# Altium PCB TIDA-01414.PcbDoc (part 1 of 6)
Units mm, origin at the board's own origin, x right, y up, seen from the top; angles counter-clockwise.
Board outline 400 x 135 mm, 4 copper layers (Top Copper, Copper Layer 2, Copper Layer 3, Bottom Copper), stack 1.567 mm thick; 835 components, 519 nets, 2420 pads, 2045 vias.
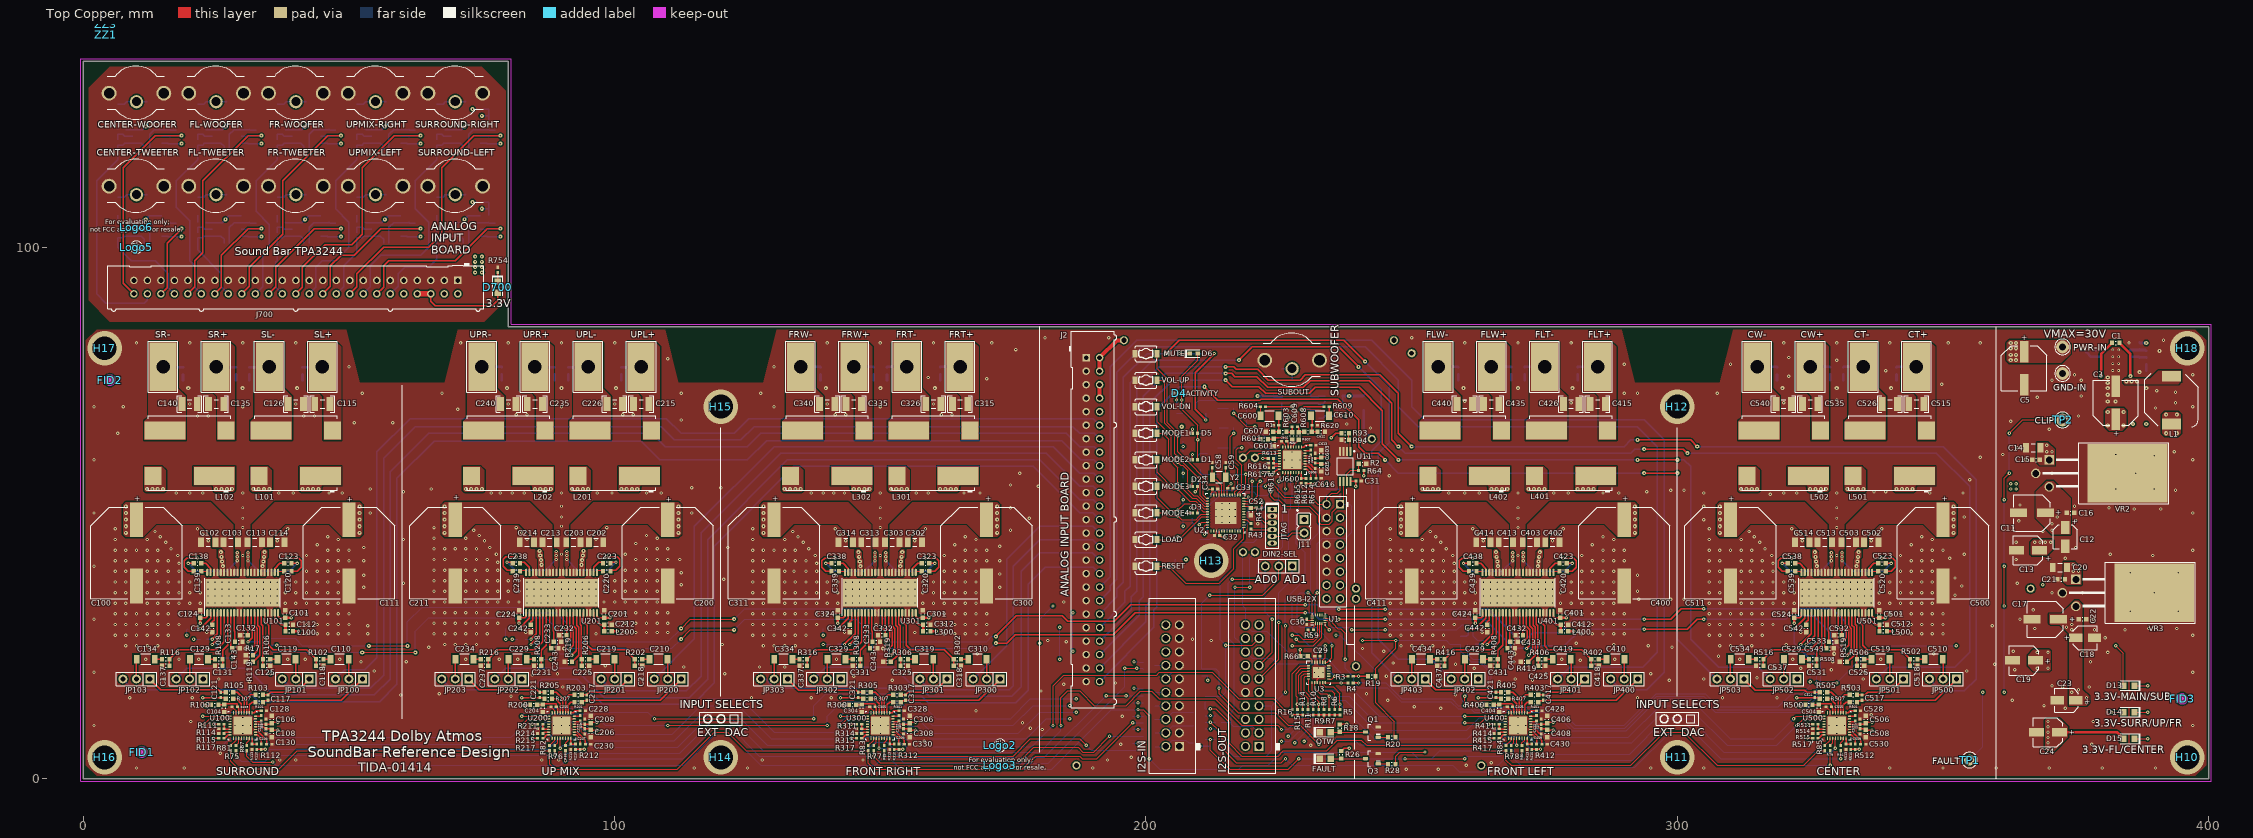
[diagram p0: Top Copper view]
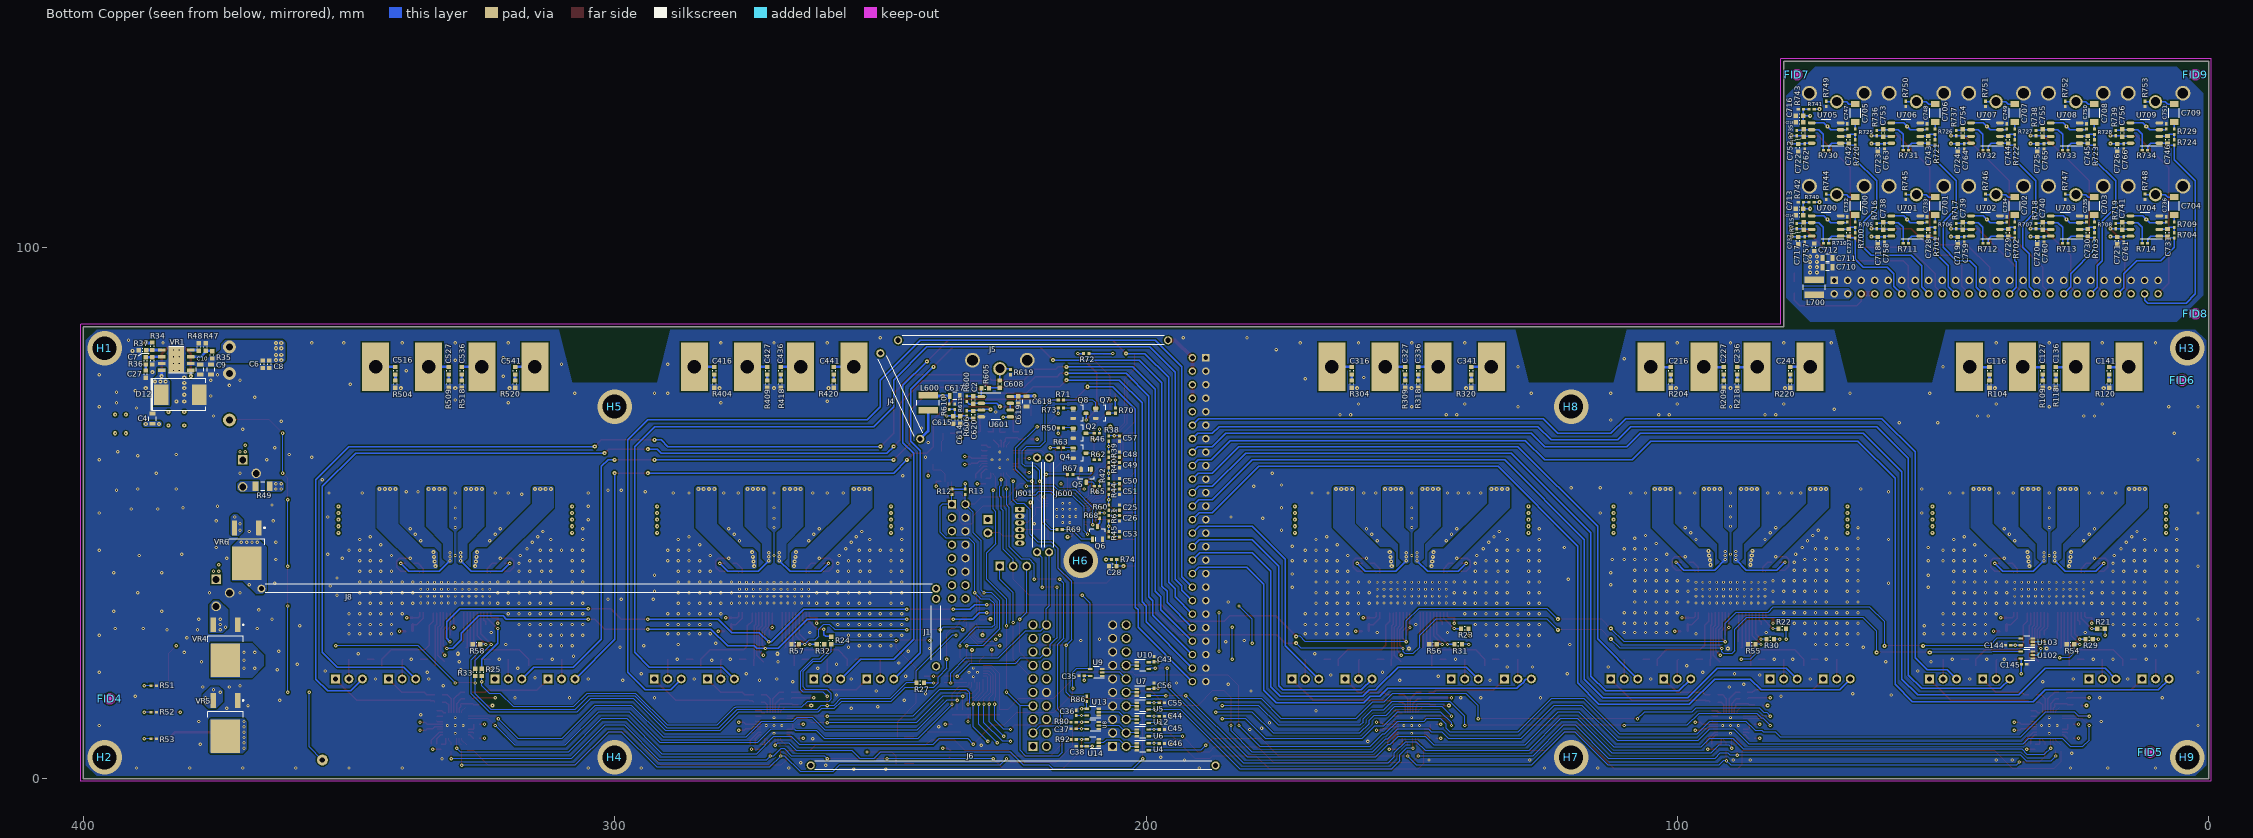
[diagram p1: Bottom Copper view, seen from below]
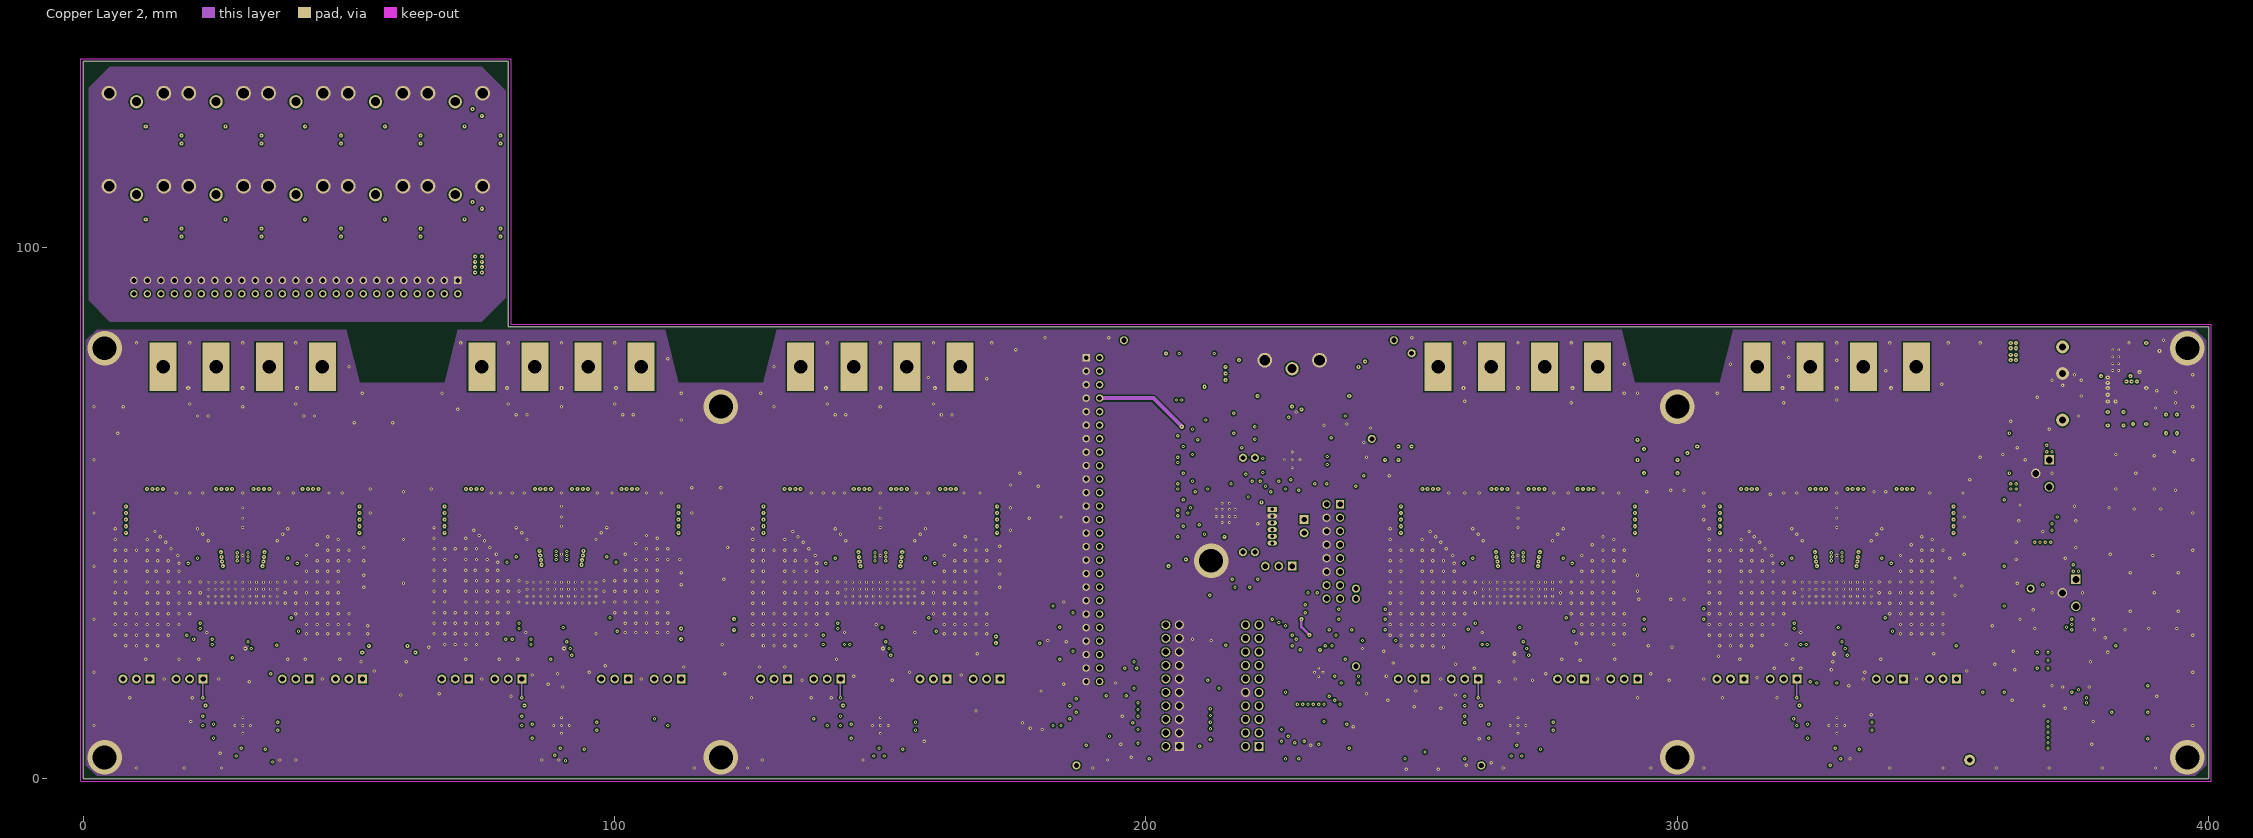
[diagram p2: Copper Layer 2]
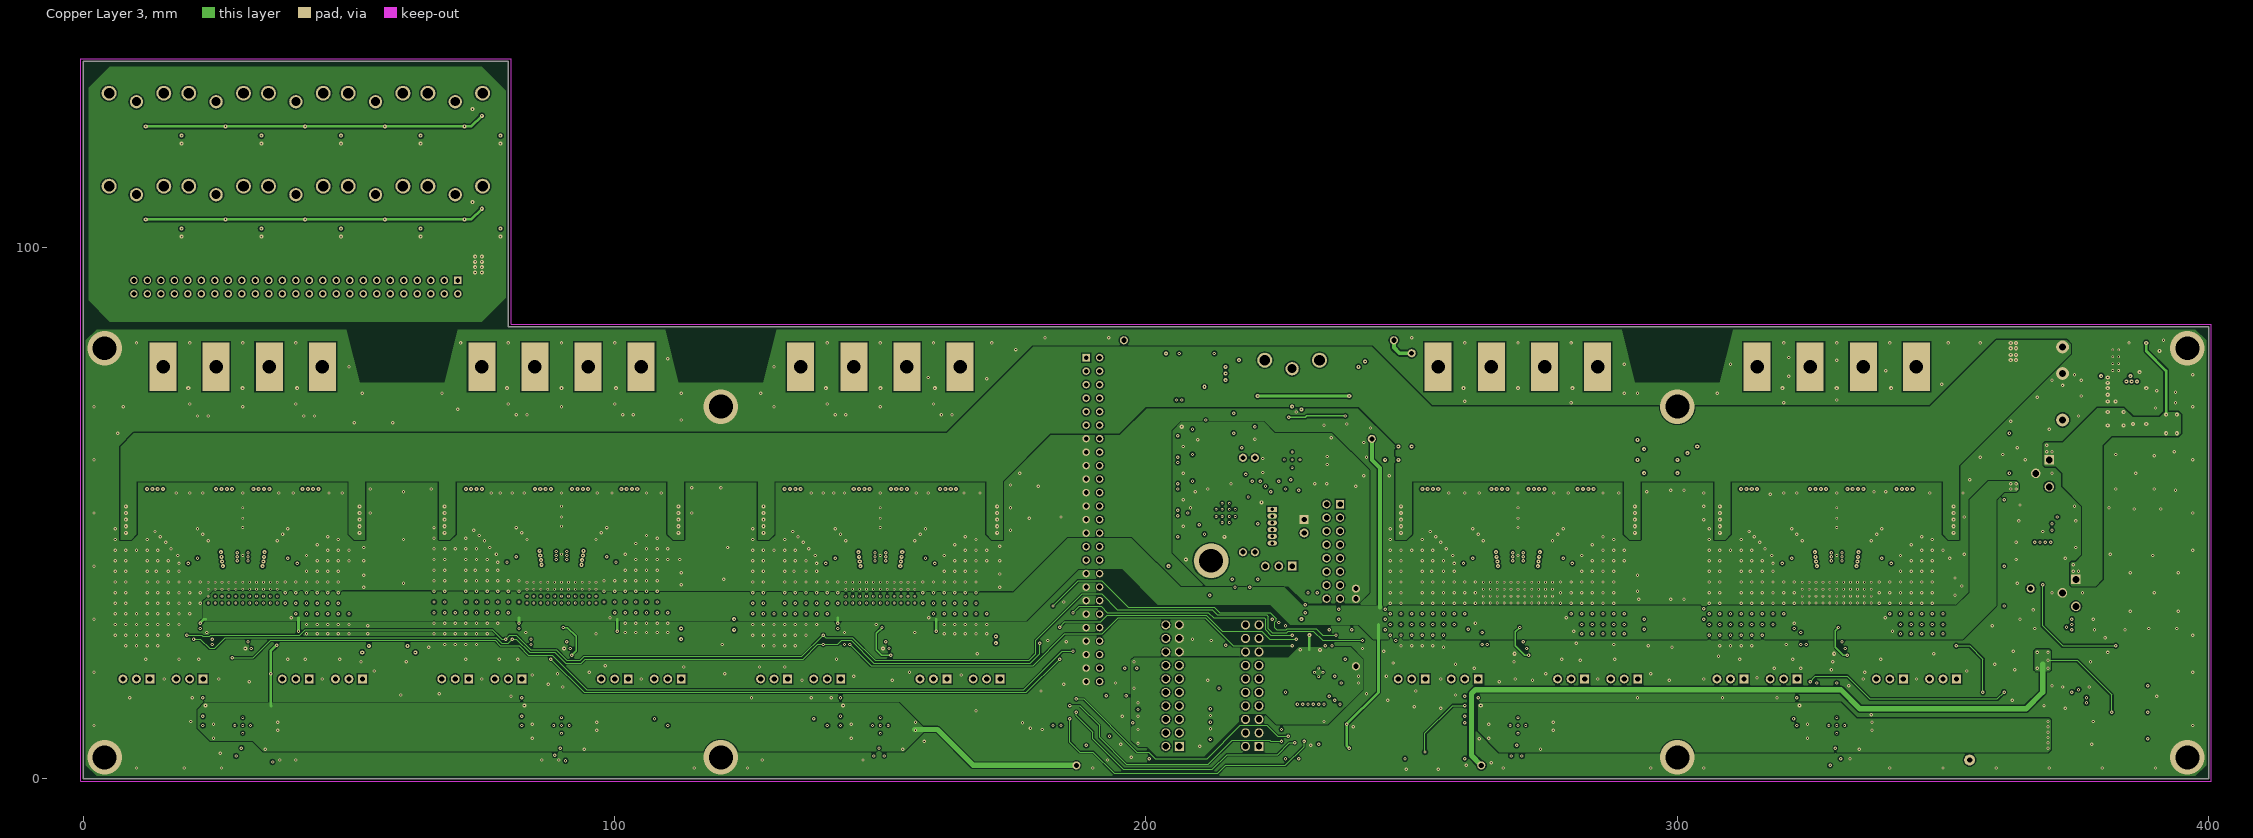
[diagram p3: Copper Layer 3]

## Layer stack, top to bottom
Top SolderMask: solder mask 0.0102, Solder Resist, Dk 3.5
Top Copper: signal copper 0.0696
Dielectric 1: prepreg 0.2032, FR-4, Dk 4.2
Copper Layer 2: signal copper 0.0356
Dielectric 2: core 0.9505, FR-4, Dk 4.2
Copper Layer 3: signal copper 0.0356
Dielectric 3: prepreg 0.2032, FR-4, Dk 4.2
Bottom Copper: signal copper 0.0696
Bottom SolderMask: solder mask 0.0102, Solder Resist, Dk 3.5

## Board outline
0,0 400,0 400,85 80,85 80,135 0,135

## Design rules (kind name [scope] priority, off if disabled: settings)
AcuteAngle [All] p1: minimum=4.50000000000000E+0001 checktracksonly=FALSE
AssemblyTestPointUsage [All] p1: valid=2
BoardOutlineClearance BoardOutlineClearance_MountingHoles [OnCopper and InComponentClass('Mounting Holes')] p1: gap=0.25
BoardOutlineClearance BoardOutlineClearance_Poly [OnCopper and IsPoly] p2: gap=0.25
BoardOutlineClearance [OnCopper and Not InComponentClass('Logo') and not InComponentClass('FiducialMark') and not InRegion(1000,500,4000,800) and not InPoly] p3: gap=0.25
Clearance Clearance_Keepouts [((IsTrack Or IsArc) And Not InPoly) And IsFree and IsKeepOut vs ((IsTrack Or IsArc) And Not InPoly) And IsFree and IsKeepOut] p1: gap=0
Clearance Clearance_Poly [InPolygon] p2: gap=0.25
Clearance [All] p3: gap=0.2
ComponentClearance ComponentClearance_MountingHoles_FiducialMarks [InComponentClass('Mounting Holes') vs InComponentClass('FiducialMark')] p1: gap=0.5 collisioncheckmode=3 verticalgap=0 showdistances=FALSE
ComponentClearance ComponentClearance_Shunt [InComponentClass('Header') vs InComponentClass('Shunt')] p2: gap=0 collisioncheckmode=3 verticalgap=0 showdistances=FALSE
ComponentClearance ComponentClearance_Logo [InComponentClass('Logo')] p3: gap=1 collisioncheckmode=3 verticalgap=0 showdistances=FALSE
ComponentClearance ComponentClearance_ScrewToNut [(HasFootprint('NY PMS 440 0025 PH')) vs (HasFootprint('Keystone_1902C'))] p4: gap=0 collisioncheckmode=3 verticalgap=0 showdistances=FALSE
ComponentClearance ComponentClearance_MountingHoles [InComponentClass('Mounting Holes')] p5: gap=0.5 collisioncheckmode=3 verticalgap=2540 showdistances=FALSE
ComponentClearance ComponentClearance_SmallPassives [HasFootprint('0201*') or HasFootprint('0402*') or HasFootprint('0508') or HasFootprint('0603*') or HasFootprint('0612') or HasFootprint('0805*') or HasFootprint('0815*') or HasFootprint('0830*') or HasFootprint('1206*') or HasFootprint('1210*') or HasFootprint('1808*') or HasFootprint('1812*') or HasFootprint('1825*') or HasFootprint('2010*') or HasFootprint('2220*') or HasFootprint('2225*') or HasFootprint('2512*') or HasFootprint('2728*') or HasFootprint('3518*') or HasFootprint('D0*') or  HasFootprint('DCK*') or HasFootprint('DDW*') or  HasFootprint('NRS*') or HasFootprint('RGE*') or HasFootprint('RGZ*') or HasFootprint('RHB*') or HasFootprint('RSV*') or HasFootprint('SOT*') or HasFootprint('TSSOP*') vs HasFootprint('0201*') or HasFootprint('0402*') or HasFootprint('0508') or HasFootprint('0603*') or HasFootprint('0612') or HasFootprint('0805*') or HasFootprint('0815*') or HasFootprint('0830*') or HasFootprint('1206*') or HasFootprint('1210*') or HasFootprint('1808*') or HasFootprint('1812*') or HasFootprint('1825*') or HasFootprint('2010*') or HasFootprint('2220*') or HasFootprint('2225*') or HasFootprint('2512*') or HasFootprint('2728*') or HasFootprint('3518*') or HasFootprint('D0*') or  HasFootprint('DCK*') or HasFootprint('DDW*') or  HasFootprint('NRS*') or HasFootprint('RGE*') or HasFootprint('RGZ*') or HasFootprint('RHB*') or HasFootprint('RSV*') or HasFootprint('SOT*') or HasFootprint('TSSOP*')] p6: gap=0.25 collisioncheckmode=3 verticalgap=0 showdistances=FALSE
ComponentClearance ComponentClearance_THtoSMT [IsThruComponent vs IsSMTComponent] p7: gap=0.25 collisioncheckmode=3 verticalgap=0 showdistances=FALSE
ComponentClearance ComponentClearance_THtoTH [IsThruComponent vs IsThruComponent] p8: gap=0.25 collisioncheckmode=3 verticalgap=0 showdistances=FALSE
DiffPairsRouting [All] p1: maxlimit=2.54 minlimit=0.254 mostfreqgap=0.254 toplayer_minwidth=0.381 toplayer_maxwidth=0.381 toplayer_prefwidth=0.381 midlayer1_minwidth=0.381 midlayer1_maxwidth=0.381 midlayer1_prefwidth=0.381 midlayer2_minwidth=0.381 midlayer2_maxwidth=0.381 midlayer2_prefwidth=0.381 bottomlayer_minwidth=0.381 bottomlayer_maxwidth=0.381 bottomlayer_prefwidth=0.381 maxuncoupledlength=25.4
FabricationTestPointUsage TestPointUsage [All] p1: valid=2 allowmultiple=FALSE
FabricationTestpoint Testpoint [All] p1: side=3 testpointundercomponent=TRUE minsize=1.016 maxsize=2.54 preferedsize=1.524 minholesize=0 maxholesize=1.016 preferedholesize=0.813 testpointgrid=0.025 allowsidetop=TRUE allowsidebottom=TRUE usegrid=TRUE gridtolerance=0
FanoutControl Fanout_LCC [IsLCC] p1: bgadir=Out bgaviamode=Centered fanoutstyle=Auto fanoutdirection=Alternating viagrid=0.025 // Fanout_LCC (Default Rule)
FanoutControl Fanout_BGA [IsBGA] p2: bgadir=Out bgaviamode=Centered fanoutstyle=Auto fanoutdirection=Alternating viagrid=0.025 // Fanout_BGA (Default Rule)
FanoutControl Fanout_Default [All] p4: bgadir=Out bgaviamode=Centered fanoutstyle=Auto fanoutdirection=Alternating viagrid=0.025 // Fanout_Default (Default Rule)
FanoutControl Fanout_Small [(CompPinCount < 5)] p5: bgadir=Out bgaviamode=Centered fanoutstyle=Auto fanoutdirection=OutThenIn viagrid=0.025 // Fanout_Small (Default Rule)
HoleSize [All] p1: absolutevalues=TRUE maxlimit=6.375 minlimit=0.2 maxpercent=80.000 minpercent=20.000
MinimumAnnularRing MinimumAnnularRing_ThermalPadVias [IsVia and InAnyComponent] p1: minimumring=0.15
MinimumAnnularRing [All] p2: minimumring=0.127
MinimumSolderMaskSliver "MinMaskSliver LibErrors" [HasFootprint('RSV0016A')] p1: minsoldermaskwidth=0.076
MinimumSolderMaskSliver MinimumSolderMaskSliver_Logo [InComponentClass('Logo') vs InComponentClass('Logo')] p2: minsoldermaskwidth=0.018
MinimumSolderMaskSliver [All] p3: minsoldermaskwidth=0.102
PlaneConnect [All] p1: planeconnectstyle=Relief reliefexpansion=0.254 reliefentries=4 reliefconductorwidth=0.254 reliefairgap=0.254
PolygonConnect PreFlood [All] p1: connectstyle=Direct reliefconductorwidth=0.254 reliefentries=4 polygonreliefangle="90 Angle" airgapwidth=0.254
RoutingVias ThermalPadVias [IsVia and InAnyComponent] p1: holewidth=0.2 width=0.5 viastyle="Through Hole" minholewidth=0.2 minwidth=0.5 maxholewidth=0.33 maxwidth=0.6
RoutingVias [All] p2: holewidth=0.254 width=0.635 viastyle="Through Hole" minholewidth=0.2 minwidth=0.508 maxholewidth=4.5 maxwidth=6.5
SilkToBoardRegionClearance [Not ((IsComment or IsDesignator) And (Hide <> 'False')) and not InRegion(1000,500,4000,800)] p1:
SilkToSilkClearance SilkToSilkClearance_Pb-FreeLogo [(HasFootprint('Pb-Free_Overlay_Medium') OR HasFootprint('Pb-Free_Overlay_Small')) vs (HasFootprint('Pb-Free_Overlay_Medium') OR HasFootprint('Pb-Free_Overlay_Small'))] p1: silktosilkclearance=0
SilkToSilkClearance [All] p2: silktosilkclearance=0.102
SilkToSolderMaskClearance SilkToComponentPadClearance [IsPad and InAnycomponent] p1: minsilkscreentomaskgap=0.102 clearancetoexposedcopper=TRUE
SilkToSolderMaskClearance "Silk to Solder Mask Opening" [All] p2: minsilkscreentomaskgap=0.102 clearancetoexposedcopper=FALSE
SolderMaskExpansion [All] p1: expansion=0.05
Width [All] p1: maxlimit=2.54 minlimit=0.152 preferedwidth=0.254 checkconnectedcopper=TRUE
15 further rules are at their usual default settings.

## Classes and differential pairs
component class TIDA-01414_UpChannel: C200 C201 C202 C203 C204 C205 C206 C207 C208 C209 C210 C211 C212 C213 C214 C215 C216 C217 C218 C219 C220 C221 C222 C223 C224 C225 C226 C227 C228 C229 C230 C231 C232 C233 C234 C235 C236 C237 C238 C239 C240 C241 C242 C243 JP200 JP201 JP202 JP203 L200 L201 L202 R200 R201 R202 R203 R204 R205 R206 R207 R208 R209 R210 R211 R212 R213 R214 R215 R216 R217 R218 R219 R220 U200 U201 UPL+ UPL- UPR+ UPR-
component class TIDA-01414_SurroundChannel: C100 C101 C102 C103 C104 C105 C106 C107 C108 C109 C110 C111 C112 C113 C114 C115 C116 C117 C118 C119 C120 C121 C122 C123 C124 C125 C126 C127 C128 C129 C130 C131 C132 C133 C134 C135 C136 C137 C138 C139 C140 C141 C142 C143 C144 C145 J2 JP100 JP101 JP102 JP103 L100 L101 L102 R17 R100 R101 R102 R103 R104 R105 R106 R107 R108 R109 R110 R111 R112 R113 R114 R115 R116 R117 R118 R119 R120 SL+ SL- SR+ SR- U100 U101 U102 U103
component class TIDA-01414_SubWooferChannel: C2 C600 C601 C602 C603 C604 C605 C606 C607 C608 C609 C610 C611 C612 C613 C614 C615 C616 C617 C618 C619 C620 DIN2-SEL I2S-OUT J600 J601 L600 R1 R600 R601 R602 R603 R604 R605 R606 R607 R608 R609 R610 R611 R612 R613 R614 R615 R616 R617 R618 R619 R620 SUBOUT U600 U601
component class TIDA-01414_ClockDrivers: C35 C36 C37 C38 C43 C44 C45 C46 FAULT I2S-IN OTW Q1 Q3 R18 R19 R20 R21 R22 R23 R24 R25 R26 R27 R28 R29 R30 R31 R32 R33 R75 R76 R77 R78 R79 R80 R81 R82 R83 R84 R85 R86 R87 R88 R89 R90 R91 R92 TP1 TP2 U4 U5 U6 U7 U8 U9 U10 U12 U13 U14
component class TIDA-01414_FrontRightChannel: C300 C301 C302 C303 C304 C305 C306 C307 C308 C309 C310 C311 C312 C313 C314 C315 C316 C317 C318 C319 C320 C321 C322 C323 C324 C325 C326 C327 C328 C329 C330 C331 C332 C333 C334 C335 C336 C337 C338 C339 C340 C341 C342 C343 FRT+ FRT- FRW+ FRW- JP300 JP301 JP302 JP303 L300 L301 L302 R300 R301 R302 R303 R304 R305 R306 R307 R308 R309 R310 R311 R312 R313 R314 R315 R316 R317 R318 R319 R320 U300 U301
component class TIDA-01414_Control: C25 C26 C28 C29 C30 C31 C32 C33 C34 C48 C49 C50 C51 C52 C53 C55 C56 C57 C58 C59 D1 D2 D3 D4 D5 D6 J11 JTAG LOAD MODE1 MODE2 MODE3 MODE4 MUTE Q2 Q4 Q5 Q6 Q7 Q8 R2 R3 R4 R5 R6 R7 R8 R9 R10 R11 R12 R13 R14 R15 R16 R38 R39 R40 R41 R42 R43 R44 R45 R46 R50 R54 R55 R56 R57 R58 R59 R60 R61 R62 R63 R64 R65 R66 R67 R68 R69 R70 R71 R72 R73 R74 R93 R94 RESET U1 U2 U3 U11 USB-I2X VOL-DN VOL-UP Y2
component class TIDA-01414_CenterChannel: C500 C501 C502 C503 C504 C505 C506 C507 C508 C509 C510 C511 C512 C513 C514 C515 C516 C517 C518 C519 C520 C521 C522 C523 C524 C525 C526 C527 C528 C529 C530 C531 C532 C533 C534 C535 C536 C537 C538 C539 C540 C541 C542 C543 CT+ CT- CW+ CW- JP500 JP501 JP502 JP503 L500 L501 L502 R500 R501 R502 R503 R504 R505 R506 R507 R508 R509 R510 R511 R512 R513 R514 R515 R516 R517 R518 R519 R520 U500 U501
component class AssemblyNote: ZZ1 ZZ2 ZZ3 ZZ?
component class FiducialMark: FID1 FID2 FID3 FID4 FID5 FID6 FID7 FID8 FID9 FID?
component class TIDA-01414_TID_Hardware: FID1 FID2 FID3 FID4 FID5 FID6 FID7 FID8 FID9 H1 H2 H3 H4 H5 H6 H7 H8 H9 H10 H11 H12 H13 H14 H15 H16 H17 H18 H? Logo2 Logo3 Logo5 Logo6 ZZ1 ZZ2 ZZ3
component class Header: DIN2-SEL J11 JP100 JP101 JP102 JP103 JP200 JP201 JP202 JP203 JP300 JP301 JP302 JP303 JP400 JP401 JP402 JP403 JP500 JP501 JP502 JP503
component class TIDA-01414_FrontLeftChannel: C400 C401 C402 C403 C404 C405 C406 C407 C408 C409 C410 C411 C412 C413 C414 C415 C416 C417 C418 C419 C420 C421 C422 C423 C424 C425 C426 C427 C428 C429 C430 C431 C432 C433 C434 C435 C436 C437 C438 C439 C440 C441 C442 C443 FLT+ FLT- FLW+ FLW- JP400 JP401 JP402 JP403 L400 L401 L402 R400 R401 R402 R403 R404 R405 R406 R407 R408 R409 R410 R411 R412 R413 R414 R415 R416 R417 R418 R419 R420 U400 U401
component class TIDA-01414_Analog-Input_DaughterCard: C700 C701 C702 C703 C704 C705 C706 C707 C708 C709 C710 C711 C712 C713 C714 C715 C716 C717 C718 C719 C720 C721 C722 C723 C724 C725 C726 C727 C728 C729 C730 C731 C732 C733 C734 C735 C736 C737 C738 C739 C740 C741 C742 C743 C744 C745 C746 C747 C748 C749 C750 C751 C752 C753 C754 C755 C756 C757 C758 C759 C760 C761 C762 C763 C764 C765 C766 CENTER-TWEETER CENTER-WOOFER D700 FL-TWEETER FL-WOOFER FR-TWEETER FR-WOOFER J700 L700 R700 R701 R702 R703 R704 R705 R706 R707 R708 R709 R710 R711 R712 R713 R714 R715 R716 R717 R718 R719 R720 R721 R722 R723 R724 R725 R726 R727 R728 R729 R730 R731 R732 R733 R734 R735 R736 R737 R738 R739 R740 R741 R742 R743 R744 R745 R746 R747 R748 R749 R750 R751 R752 R753 R754 SURROUND-LEFT SURROUND-RIGHT U700 U701 U702 U703 U704 U705 U706 U707 U708 U709 UPMIX-LEFT UPMIX-RIGHT
component class TIDA-01414_PowerSupplies: C1 C3 C4 C5 C6 C7 C8 C9 C10 C11 C12 C13 C14 C15 C16 C17 C18 C19 C20 C21 C22 C23 C24 C27 D12 D13 D14 D15 GND-IN J1 J4 J5 J6 J8 L1 PWR-IN R34 R35 R36 R37 R47 R48 R49 R51 R52 R53 VR1 VR2 VR3 VR4 VR5 VR6

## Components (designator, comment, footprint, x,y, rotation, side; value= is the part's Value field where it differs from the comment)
C1 "C0603C104K5RACTU" 0603L 382.5,82 r0 top
C2 "GRM1885C1H220JA01D" 0603L 232.5,71.25 r90 bottom
C3 "+" SM_RADIAL_E 382.5,70.75 r90 top
C4 "C2012X7R1H225K125AC" 0805_KTR 387,67.75 r90 bottom
C5 "+" SM_RADIAL_E 365.25,77.25 r270 top
C6 "UMK107AB7105KA-T" 0603L 366.25,78 r90 bottom
C7 "GRM1885C1H750JA01D" 0603L 387,78.625 r270 bottom
C8 "C0603C103K5RACTU" 0603L 365,78 r270 bottom
C9 "C2012X7R1H225K125AC" 0805_KTR 376,77 r270 bottom
C10 "C2012X7R1H225K125AC" 0805_KTR 378,77 r270 bottom
C11 "+" SM_RADIAL_D 366.75,50 r180 top
C12 "+" SM_RADIAL_B 373,45.5 r270 top
C13 "+" SM_RADIAL_C 366,43 r180 top
C14 "GRM31CR71E475KA88L" 1206_180L 367,62.25 r180 top
C15 "GRM188R71E474KA12D" 0603L 367.5,60 r180 top
C16 "C0603C104K5RACTU" 0603L 374,50 r180 top
C17 "+" SM_RADIAL_D 369.25,30 r180 top
C18 "+" SM_RADIAL_B 376.75,26.5 r0 top
C19 "+" SM_RADIAL_C 365.25,22.25 r180 top locked
C20 "GRM31CR71E475KA88L" 1206_180L 372,39.75 r180 top
C21 "GRM188R71E474KA12D" 0603L 372.25,37.5 r180 top
C22 "C0603C104K5RACTU" 0603L 376.25,30 r180 top
C23 "+" SM_RADIAL_B 373.25,14.75 r180 top
C24 "+" SM_RADIAL_C 369.75,8.75 r180 top
C25 "GRM1555C1E471JA01D" 0402L 205,51 r90 bottom
C26 "GRM1555C1E471JA01D" 0402L 205,49 r270 bottom
C27 "GRM1885C1H362JA01D" 0603L 388.25,76.125 r270 bottom
C28 "885012206036" 0603L 206.25,40 r180 bottom
C29 "GRM155R71A104KA01D" 0402L 232.25,23 r0 top
C30 "GRM155R71A104KA01D" 0402L 230.25,29.5 r90 top
C31 "GRM155R71A104KA01D" 0402L 240,56 r180 top
C32 "GRM155R71A104KA01D" 0402L 213.375,45.75 r0 top
C33 "GRM155R71A104KA01D" 0402L 215.875,54.625 r180 top
C34 "GRM155R71A104KA01D" 0402L 213,54.5 r180 top
C35 "C1005X5R0J105M050BB" 0402L 212.125,19.375 r180 bottom
C36 "GRM155R71A104KA01D" 0402L 213.125,12.375 r270 bottom
C37 "GRM155R71A104KA01D" 0402L 213.625,9.375 r180 bottom
C38 "GRM155R71A104KA01D" 0402L 212.625,6.125 r180 bottom
C43 "GRM155R71A104KA01D" 0402L 198.5,22.5 r270 bottom
C44 "GRM155R71A104KA01D" 0402L 197,11.75 r0 bottom
C45 "GRM155R71A104KA01D" 0402L 197,9.25 r0 bottom
C46 "GRM155R71A104KA01D" 0402L 197,6.625 r0 bottom
C48 "GRM1555C1E471JA01D" 0402L 205,61 r90 bottom
C49 "GRM1555C1E471JA01D" 0402L 205,59 r270 bottom
C50 "GRM1555C1E471JA01D" 0402L 205,56 r90 bottom
C51 "GRM1555C1E471JA01D" 0402L 205,54 r270 bottom
C52 "885012206036" 0603L 219.75,50.25 r90 top
C53 "GRM1555C1E471JA01D" 0402L 205,46 r90 bottom
C55 "C1005X5R0J105M050BB" 0402L 197,14.25 r0 bottom
C56 "GRM155R71A104KA01D" 0402L 198.5,17.5 r270 bottom
C57 "GRM1555C1E471JA01D" 0402L 205,64 r270 bottom
C58 "GRM1555C1H120JA01D" 0402L 212.5,59 r270 top
C59 "GRM1555C1H120JA01D" 0402L 215,59 r270 top
C100 "+" SM_RADIAL_J16 10,42.5 r270 top locked
C101 "C0603C104K5RACTU" 0603L 38,31 r90 top
C102 "GRM31MR71H105KA88L" 1206L 23.5,44.5 r0 top
C103 "GRM31MR71H105KA88L" 1206L 27.75,44.5 r180 top
C104 "GRM188R61A106ME69D" 0603L 26.5,13.25 r270 top
C105 "GRM155R71A104KA01D" 0402L 28.5,13.5 r180 top
C106 "GRM188R61A106ME69D" 0603L 35.5,11.125 r90 top
C107 "GRM155R71A104KA01D" 0402L 34.375,10.75 r90 top
C108 "GRM188R61A106ME69D" 0603L 35.5,8.5 r270 top
C109 "GRM155R71A104KA01D" 0402L 34.375,8.875 r270 top
C110 "GRM31CR71C106KAC7L" 1206_180 48.25,22.5 r180 top
C111 "+" SM_RADIAL_J16 50,42.5 r270 top locked
C112 "C0603C104K5RACTU" 0603L 38.75,29 r0 top
C113 "GRM31MR71H105KA88L" 1206L 32.25,44.5 r0 top
C114 "GRM31MR71H105KA88L" 1206L 36.5,44.5 r180 top
C115 "C3225X7R2A105K200AA" 1210_220 45,70.5 r180 top
C116 "C0603C103K5RACTU" 0603L 41.25,76.75 r270 bottom
C117 "GRM1555C1H102JA01D" 0402L 34.75,15.25 r90 top
C118 "GRM1885C1H101JA01D" 0603L 44.5,21.25 r0 top
C119 "GRM31CR71C106KAC7L" 1206_180 38.25,22.5 r180 top
C120 "GRM188R71E333KA01D" 0603L 38.5,39 r180 top
C121 "GRM1555C1H102JA01D" 0402L 25.875,15.75 r270 top
C122 "C1005X5R1A225K050BC" 0402L 33.5,11.375 r90 top
C123 "GRM188R71E333KA01D" 0603L 38.5,40.5 r180 top
C124 "C0603C104K5RACTU" 0603L 22,31 r90 top
C125 "GRM1885C1H101JA01D" 0603L 34.5,21.25 r0 top
C126 "C3225X7R2A105K200AA" 1210_220 40,70.5 r0 top
C127 "C0603C103K5RACTU" 0603L 31.25,76.75 r270 bottom
C128 "C1005X5R1A225K050BC" 0402L 34,12.75 r0 top
C129 "GRM31CR71C106KAC7L" 1206_180 21.75,22.5 r0 top
C130 "GRM155R71A104KA01D" 0402L 35,6.5 r0 top
C131 "GRM1885C1H101JA01D" 0603L 25.5,21.25 r180 top
C132 "GRM188R71C105KA12D" 0603L 30.25,27 r0 top
C133 "GRM188R71C105KA12D" 0603L 29.25,25.75 r180 top
C134 "GRM31CR71C106KAC7L" 1206_180 11.75,22.5 r0 top
C135 "C3225X7R2A105K200AA" 1210_220 25,70.5 r180 top
C136 "C0603C103K5RACTU" 0603L 28.75,76.75 r270 bottom
C137 "GRM1885C1H101JA01D" 0603L 15.5,21.25 r180 top
C138 "GRM188R71E333KA01D" 0603L 21.5,40.5 r0 top
C139 "GRM188R71E333KA01D" 0603L 21.5,39 r0 top
C140 "C3225X7R2A105K200AA" 1210_220 20,70.5 r0 top
C141 "C0603C103K5RACTU" 0603L 18.75,76.75 r270 bottom
C142 "C0603C104K5RACTU" 0603L 24.25,28.25 r90 top
C143 "GRM188R71H473KA61D" 0603L 28.75,24.5 r0 top
C144 "GRM155R71A104KA01D" 0402L 37.75,25.125 r180 bottom
C145 "GRM155R71A104KA01D" 0402L 34.75,21.5 r0 bottom
C200 "+" SM_RADIAL_J16 110,42.5 r270 top locked
C201 "C0603C104K5RACTU" 0603L 98,31 r90 top
C202 "GRM31MR71H105KA88L" 1206L 96.5,44.5 r180 top
C203 "GRM31MR71H105KA88L" 1206L 92.25,44.5 r0 top
C204 "GRM188R61A106ME69D" 0603L 86.5,13.25 r270 top
C205 "GRM155R71A104KA01D" 0402L 88.5,13.5 r180 top
C206 "GRM188R61A106ME69D" 0603L 95.5,8.5 r270 top
C207 "GRM155R71A104KA01D" 0402L 94.375,8.875 r270 top
C208 "GRM188R61A106ME69D" 0603L 95.5,11.125 r90 top
C209 "GRM155R71A104KA01D" 0402L 94.375,10.75 r90 top
C210 "GRM31CR71C106KAC7L" 1206_180 108.25,22.5 r180 top
C211 "+" SM_RADIAL_J16 70,42.5 r270 top locked
C212 "C0603C104K5RACTU" 0603L 98.75,29 r0 top
C213 "GRM31MR71H105KA88L" 1206L 87.75,44.5 r180 top
C214 "GRM31MR71H105KA88L" 1206L 83.5,44.5 r0 top
C215 "C3225X7R2A105K200AA" 1210_220 105,70.5 r180 top
C216 "C0603C103K5RACTU" 0603L 101.25,76.75 r270 bottom
C217 "GRM1555C1H102JA01D" 0402L 94.75,15.25 r90 top
C218 "GRM1885C1H101JA01D" 0603L 104.5,21.25 r0 top
C219 "GRM31CR71C106KAC7L" 1206_180 98.25,22.5 r180 top
C220 "GRM188R71E333KA01D" 0603L 98.5,39 r180 top
C221 "GRM1555C1H102JA01D" 0402L 85.875,15.75 r270 top
C222 "C1005X5R1A225K050BC" 0402L 93.5,11.375 r90 top
C223 "GRM188R71E333KA01D" 0603L 98.5,40.5 r180 top
C224 "C0603C104K5RACTU" 0603L 82,31 r90 top
C225 "GRM1885C1H101JA01D" 0603L 94.5,21.25 r0 top
C226 "C3225X7R2A105K200AA" 1210_220 100,70.5 r0 top
C227 "C0603C103K5RACTU" 0603L 91.25,76.75 r270 bottom
C228 "C1005X5R1A225K050BC" 0402L 94,12.75 r0 top
C229 "GRM31CR71C106KAC7L" 1206_180 81.75,22.5 r0 top
C230 "GRM155R71A104KA01D" 0402L 95,6.5 r0 top
C231 "GRM1885C1H101JA01D" 0603L 85.5,21.25 r180 top
C232 "GRM188R71C105KA12D" 0603L 90.25,27 r0 top
C233 "GRM188R71C105KA12D" 0603L 89.25,25.75 r180 top
C234 "GRM31CR71C106KAC7L" 1206_180 71.75,22.5 r0 top
C235 "C3225X7R2A105K200AA" 1210_220 85,70.5 r180 top
C236 "C0603C103K5RACTU" 0603L 88.75,76.75 r270 bottom
C237 "GRM1885C1H101JA01D" 0603L 75.5,21.25 r180 top
C238 "GRM188R71E333KA01D" 0603L 81.5,40.5 r0 top
C239 "GRM188R71E333KA01D" 0603L 81.5,39 r0 top
C240 "C3225X7R2A105K200AA" 1210_220 80,70.5 r0 top
C241 "C0603C103K5RACTU" 0603L 78.75,76.75 r270 bottom
C242 "C0603C104K5RACTU" 0603L 84.25,28.25 r90 top
C243 "GRM188R71H473KA61D" 0603L 88.75,24.5 r0 top
C300 "+" SM_RADIAL_J16 170,42.5 r270 top locked
C301 "C0603C104K5RACTU" 0603L 158,31 r90 top
C302 "GRM31MR71H105KA88L" 1206L 156.5,44.5 r180 top
C303 "GRM31MR71H105KA88L" 1206L 152.25,44.5 r0 top
C304 "GRM188R61A106ME69D" 0603L 146.5,13.25 r270 top
C305 "GRM155R71A104KA01D" 0402L 148.5,13.5 r180 top
C306 "GRM188R61A106ME69D" 0603L 155.5,11.125 r90 top
C307 "GRM155R71A104KA01D" 0402L 154.375,10.75 r90 top
C308 "GRM188R61A106ME69D" 0603L 155.5,8.5 r270 top
C309 "GRM155R71A104KA01D" 0402L 154.375,8.875 r270 top
C310 "GRM31CR71C106KAC7L" 1206_180 168.25,22.5 r180 top
C311 "+" SM_RADIAL_J16 130,42.5 r270 top locked
C312 "C0603C104K5RACTU" 0603L 158.75,29 r0 top
C313 "GRM31MR71H105KA88L" 1206L 147.75,44.5 r180 top
C314 "GRM31MR71H105KA88L" 1206L 143.5,44.5 r0 top
C315 "C3225X7R2A105K200AA" 1210_220 165,70.5 r180 top
C316 "C0603C103K5RACTU" 0603L 161.25,76.75 r270 bottom
C317 "GRM1555C1H102JA01D" 0402L 154.75,15.25 r90 top
C318 "GRM1885C1H101JA01D" 0603L 164.5,21.25 r0 top
C319 "GRM31CR71C106KAC7L" 1206_180 158.25,22.5 r180 top
C320 "GRM188R71E333KA01D" 0603L 158.5,39 r180 top
C321 "GRM1555C1H102JA01D" 0402L 145.875,15.75 r270 top
C322 "C1005X5R1A225K050BC" 0402L 153.5,11.375 r90 top
C323 "GRM188R71E333KA01D" 0603L 158.5,40.5 r180 top
C324 "C0603C104K5RACTU" 0603L 142,31 r90 top
C325 "GRM1885C1H101JA01D" 0603L 154.5,21.25 r0 top
C326 "C3225X7R2A105K200AA" 1210_220 160,70.5 r0 top
C327 "C0603C103K5RACTU" 0603L 151.25,76.75 r270 bottom
C328 "C1005X5R1A225K050BC" 0402L 154,12.75 r0 top
C329 "GRM31CR71C106KAC7L" 1206_180 141.75,22.5 r0 top
C330 "GRM155R71A104KA01D" 0402L 155,6.5 r0 top
C331 "GRM1885C1H101JA01D" 0603L 145.5,21.25 r180 top
C332 "GRM188R71C105KA12D" 0603L 150.25,27 r0 top
C333 "GRM188R71C105KA12D" 0603L 149.25,25.75 r180 top
C334 "GRM31CR71C106KAC7L" 1206_180 131.75,22.5 r0 top
C335 "C3225X7R2A105K200AA" 1210_220 145,70.5 r180 top
C336 "C0603C103K5RACTU" 0603L 148.75,76.75 r270 bottom
C337 "GRM1885C1H101JA01D" 0603L 135.5,21.25 r180 top
C338 "GRM188R71E333KA01D" 0603L 141.5,40.5 r0 top
C339 "GRM188R71E333KA01D" 0603L 141.5,39 r0 top
C340 "C3225X7R2A105K200AA" 1210_220 140,70.5 r0 top
C341 "C0603C103K5RACTU" 0603L 138.75,76.75 r270 bottom
C342 "C0603C104K5RACTU" 0603L 144.25,28.25 r90 top
C343 "GRM188R71H473KA61D" 0603L 148.75,24.5 r0 top
C400 "+" SM_RADIAL_J16 290,42.5 r270 top locked
C401 "C0603C104K5RACTU" 0603L 278,31 r90 top
C402 "GRM31MR71H105KA88L" 1206L 276.5,44.5 r180 top
C403 "GRM31MR71H105KA88L" 1206L 272.25,44.5 r0 top
C404 "GRM188R61A106ME69D" 0603L 266.5,13.25 r270 top
C405 "GRM155R71A104KA01D" 0402L 268.5,13.5 r180 top
C406 "GRM188R61A106ME69D" 0603L 275.5,11.125 r90 top
C407 "GRM155R71A104KA01D" 0402L 274.375,10.75 r90 top
C408 "GRM188R61A106ME69D" 0603L 275.5,8.5 r270 top
C409 "GRM155R71A104KA01D" 0402L 274.375,8.875 r270 top
C410 "GRM31CR71C106KAC7L" 1206_180 288.375,22.5 r180 top
C411 "+" SM_RADIAL_J16 250,42.5 r270 top locked
C412 "C0603C104K5RACTU" 0603L 278.75,29 r0 top
C413 "GRM31MR71H105KA88L" 1206L 267.75,44.5 r180 top
C414 "GRM31MR71H105KA88L" 1206L 263.5,44.5 r0 top
C415 "C3225X7R2A105K200AA" 1210_220 285,70.5 r180 top
C416 "C0603C103K5RACTU" 0603L 281.25,76.75 r270 bottom
C417 "GRM1555C1H102JA01D" 0402L 274.75,15.25 r90 top
C418 "GRM1885C1H101JA01D" 0603L 284.5,21.25 r0 top
C419 "GRM31CR71C106KAC7L" 1206_180 278.25,22.5 r180 top
C420 "GRM188R71E333KA01D" 0603L 278.5,39 r180 top
C421 "GRM1555C1H102JA01D" 0402L 265.875,15.75 r270 top
C422 "C1005X5R1A225K050BC" 0402L 273.5,11.375 r90 top
C423 "GRM188R71E333KA01D" 0603L 278.5,40.5 r180 top
C424 "C0603C104K5RACTU" 0603L 262,31 r90 top
C425 "GRM1885C1H101JA01D" 0603L 274.5,21.25 r0 top
C426 "C3225X7R2A105K200AA" 1210_220 280,70.5 r0 top
C427 "C0603C103K5RACTU" 0603L 271.25,76.75 r270 bottom
C428 "C1005X5R1A225K050BC" 0402L 274,12.75 r0 top
C429 "GRM31CR71C106KAC7L" 1206_180 261.75,22.5 r0 top
C430 "GRM155R71A104KA01D" 0402L 275,6.5 r0 top
C431 "GRM1885C1H101JA01D" 0603L 265.5,21.25 r180 top
C432 "GRM188R71C105KA12D" 0603L 270.25,27 r0 top
C433 "GRM188R71C105KA12D" 0603L 269.25,25.75 r180 top
C434 "GRM31CR71C106KAC7L" 1206_180 251.75,22.5 r0 top
C435 "C3225X7R2A105K200AA" 1210_220 265,70.5 r180 top
C436 "C0603C103K5RACTU" 0603L 268.75,76.75 r270 bottom
C437 "GRM1885C1H101JA01D" 0603L 255.5,21.25 r180 top
C438 "GRM188R71E333KA01D" 0603L 261.5,40.5 r0 top
C439 "GRM188R71E333KA01D" 0603L 261.5,39 r0 top
C440 "C3225X7R2A105K200AA" 1210_220 260,70.5 r0 top
C441 "C0603C103K5RACTU" 0603L 258.75,76.75 r270 bottom
C442 "C0603C104K5RACTU" 0603L 264.25,28.25 r90 top
C443 "GRM188R71H473KA61D" 0603L 268.75,24.5 r0 top
C500 "+" SM_RADIAL_J16 350,42.5 r270 top locked
C501 "C0603C104K5RACTU" 0603L 338,31 r90 top
C502 "GRM31MR71H105KA88L" 1206L 336.5,44.5 r180 top
C503 "GRM31MR71H105KA88L" 1206L 332.25,44.5 r0 top
C504 "GRM188R61A106ME69D" 0603L 326.625,13.25 r270 top
C505 "GRM155R71A104KA01D" 0402L 328.5,13.5 r180 top
C506 "GRM188R61A106ME69D" 0603L 335.5,11.125 r90 top
C507 "GRM155R71A104KA01D" 0402L 334.375,10.75 r90 top
C508 "GRM188R61A106ME69D" 0603L 335.5,8.5 r270 top
C509 "GRM155R71A104KA01D" 0402L 334.375,8.875 r270 top
C510 "GRM31CR71C106KAC7L" 1206_180 348.25,22.5 r180 top
C511 "+" SM_RADIAL_J16 310,42.5 r270 top locked
C512 "C0603C104K5RACTU" 0603L 338.75,29 r0 top
C513 "GRM31MR71H105KA88L" 1206L 327.75,44.5 r180 top
C514 "GRM31MR71H105KA88L" 1206L 323.5,44.5 r0 top
C515 "C3225X7R2A105K200AA" 1210_220 345,70.5 r180 top
C516 "C0603C103K5RACTU" 0603L 341.25,76.75 r270 bottom
C517 "GRM1555C1H102JA01D" 0402L 334.75,15.25 r90 top
C518 "GRM1885C1H101JA01D" 0603L 344.5,21.25 r0 top
C519 "GRM31CR71C106KAC7L" 1206_180 338.25,22.5 r180 top
C520 "GRM188R71E333KA01D" 0603L 338.5,39 r180 top
C521 "GRM1555C1H102JA01D" 0402L 325.875,15.75 r270 top
C522 "C1005X5R1A225K050BC" 0402L 333.5,11.375 r90 top
C523 "GRM188R71E333KA01D" 0603L 338.5,40.5 r180 top
C524 "C0603C104K5RACTU" 0603L 322,31 r90 top
C525 "GRM1885C1H101JA01D" 0603L 334.5,21.25 r0 top
C526 "C3225X7R2A105K200AA" 1210_220 340,70.5 r0 top
C527 "C0603C103K5RACTU" 0603L 331.25,76.75 r270 bottom
C528 "C1005X5R1A225K050BC" 0402L 334,12.75 r0 top
C529 "GRM31CR71C106KAC7L" 1206_180 321.75,22.5 r0 top
C530 "GRM155R71A104KA01D" 0402L 335,6.5 r0 top
C531 "GRM1885C1H101JA01D" 0603L 325.5,21.25 r180 top
C532 "GRM188R71C105KA12D" 0603L 330.25,27 r0 top
C533 "GRM188R71C105KA12D" 0603L 329.25,25.75 r180 top
C534 "GRM31CR71C106KAC7L" 1206_180 311.75,22.5 r0 top
C535 "C3225X7R2A105K200AA" 1210_220 325,70.5 r180 top
C536 "C0603C103K5RACTU" 0603L 328.75,76.75 r270 bottom
C537 "GRM1885C1H101JA01D" 0603L 315.5,21.25 r180 top
C538 "GRM188R71E333KA01D" 0603L 321.5,40.5 r0 top
C539 "GRM188R71E333KA01D" 0603L 321.5,39 r0 top
C540 "C3225X7R2A105K200AA" 1210_220 320,70.5 r0 top
C541 "C0603C103K5RACTU" 0603L 318.75,76.75 r270 bottom
C542 "C0603C104K5RACTU" 0603L 324.25,28.25 r90 top
C543 "GRM188R71H473KA61D" 0603L 328.75,24.5 r0 top
C600 "GRM31CR71C106KAC7L" 1206_180 223.25,68.25 r180 top
C601 "GRM188R61A106ME69D" 0603L 224,63.25 r270 top
C602 "GRM155R71A104KA01D" 0402L 226,63.5 r180 top
C603 "GRM188R61A106ME69D" 0603L 233,61.125 r90 top
C604 "GRM155R71A104KA01D" 0402L 231.875,60.75 r90 top
C605 "GRM188R61A106ME69D" 0603L 233,58.5 r270 top
C606 "GRM155R71A104KA01D" 0402L 231.875,58.875 r270 top
C607 "GRM1885C1H101JA01D" 0603L 223.25,65.25 r180 top
C608 "GRM188R61C106MAALD" 0603L 227.5,74.25 r270 bottom
C609 "GRM1555C1H102JA01D" 0402L 228,66.25 r0 top
C610 "GRM31CR71C106KAC7L" 1206_180 232.75,68.25 r0 top
C611 "C1005X5R1A225K050BC" 0402L 231,61.375 r90 top
C612 "GRM1885C1H101JA01D" 0603L 233,65.25 r0 top
C613 "C1005X5R1A225K050BC" 0402L 231.5,62.75 r0 top
C614 "GRM188R61C106MAALD" 0603L 235,67.5 r90 bottom
C615 "GRM188R61C106MAALD" 0603L 236.25,67.5 r90 bottom
C616 "GRM155R71A104KA01D" 0402L 232.5,56.5 r0 top
C617 "EMK212BJ106KG-T" 0805_KTR 236,72 r180 bottom
C618 "EMK212BJ106KG-T" 0805_KTR 222.5,71 r270 bottom
C619 "C0603C104K5RACTU" 0603L 224,71.25 r270 bottom
C620 "GRM1885C1H220JA01D" 0603L 232.5,68.5 r90 bottom
C700 "GRM31CR71C106KAC7L" 1206_180 66.5,107.75 r270 bottom
C701 "GRM31CR71C106KAC7L" 1206_180 51.5,107.75 r270 bottom locked
C702 "GRM31CR71C106KAC7L" 1206_180 36.5,107.75 r270 bottom
C703 "GRM31CR71C106KAC7L" 1206_180 21.5,107.75 r270 bottom
C704 "GRM31CR71C106KAC7L" 1206_180 6.5,107.75 r270 bottom
C705 "GRM31CR71C106KAC7L" 1206_180 66.5,125.25 r270 bottom
C706 "GRM31CR71C106KAC7L" 1206_180 51.5,125.25 r270 bottom
C707 "GRM31CR71C106KAC7L" 1206_180 36.5,125.25 r270 bottom
C708 "GRM31CR71C106KAC7L" 1206_180 21.5,125.25 r270 bottom
C709 "GRM31CR71C106KAC7L" 1206_180 6.5,125.25 r270 bottom
C710 "EMK212BJ106KG-T" 0805_KTR 71.75,96.25 r180 bottom
C711 "EMK212BJ106KG-T" 0805_KTR 71.75,98 r180 bottom
C712 "C0603C104K5RACTU" 0603L 74.25,100 r90 bottom
C713 "GRM188R61C106MAALD" 0603L 77,107.25 r180 bottom
C714 "GRM188R61C106MAALD" 0603L 77,106 r180 bottom
C715 "GRM188R61C106MAALD" 0603L 77,123.5 r180 bottom
C716 "GRM188R61C106MAALD" 0603L 77,124.75 r180 bottom
C717 "GRM188R61C106MAALD" 0603L 77.25,101.25 r90 bottom
C718 "GRM188R61C106MAALD" 0603L 62.25,101.25 r90 bottom locked
C719 "GRM188R61C106MAALD" 0603L 47.25,101.25 r90 bottom
C720 "GRM188R61C106MAALD" 0603L 32.25,101.25 r90 bottom
C721 "GRM188R61C106MAALD" 0603L 17.25,101.25 r90 bottom
C722 "GRM188R61C106MAALD" 0603L 77.25,118.75 r90 bottom
C723 "GRM188R61C106MAALD" 0603L 62.25,118.75 r90 bottom
C724 "GRM188R61C106MAALD" 0603L 47.25,118.75 r90 bottom
C725 "GRM188R61C106MAALD" 0603L 32.25,118.75 r90 bottom
C726 "GRM188R61C106MAALD" 0603L 17.25,118.75 r90 bottom
C727 "GRM1885C1H220JA01D" 0603L 67.75,102.75 r270 bottom
C728 "GRM1885C1H220JA01D" 0603L 52.75,102.75 r270 bottom
C729 "GRM1885C1H220JA01D" 0603L 37.75,102.75 r270 bottom
C730 "GRM1885C1H220JA01D" 0603L 22.75,102.75 r270 bottom
C731 "GRM1885C1H220JA01D" 0603L 7.75,102.75 r270 bottom
C732 "GRM155R71A104KA01D" 0402L 68,105.25 r270 bottom
C733 "GRM155R71A104KA01D" 0402L 53,105.25 r270 bottom locked
C734 "GRM155R71A104KA01D" 0402L 38,105.25 r270 bottom
C735 "GRM155R71A104KA01D" 0402L 23,105.25 r270 bottom
C736 "GRM155R71A104KA01D" 0402L 8,105.25 r270 bottom
C737 "GRM1885C1H220JA01D" 0603L 76.25,104 r270 bottom
C738 "GRM1885C1H220JA01D" 0603L 61.25,104 r270 bottom locked
C739 "GRM1885C1H220JA01D" 0603L 46.25,104 r270 bottom
C740 "GRM1885C1H220JA01D" 0603L 31.25,104 r270 bottom
C741 "GRM1885C1H220JA01D" 0603L 16.25,104 r270 bottom
C742 "GRM1885C1H220JA01D" 0603L 67.75,120.25 r270 bottom
C743 "GRM1885C1H220JA01D" 0603L 52.75,120.25 r270 bottom
C744 "GRM1885C1H220JA01D" 0603L 37.75,120.25 r270 bottom
C745 "GRM1885C1H220JA01D" 0603L 22.75,120.25 r270 bottom
C746 "GRM1885C1H220JA01D" 0603L 7.75,120.25 r270 bottom
C747 "GRM155R71A104KA01D" 0402L 68,122.75 r270 bottom
C748 "GRM155R71A104KA01D" 0402L 53,122.75 r270 bottom
C749 "GRM155R71A104KA01D" 0402L 38,122.75 r270 bottom
C750 "GRM155R71A104KA01D" 0402L 23,122.75 r270 bottom
C751 "GRM155R71A104KA01D" 0402L 8,122.75 r270 bottom
C752 "GRM1885C1H220JA01D" 0603L 76.25,121.5 r270 bottom
C753 "GRM1885C1H220JA01D" 0603L 61.25,121.5 r270 bottom
C754 "GRM1885C1H220JA01D" 0603L 46.25,121.5 r270 bottom
C755 "GRM1885C1H220JA01D" 0603L 31.25,121.5 r270 bottom
C756 "GRM1885C1H220JA01D" 0603L 16.25,121.5 r270 bottom
C757 "GRM155R71A104KA01D" 0402L 76,101.5 r90 bottom
C758 "GRM155R71A104KA01D" 0402L 61,101.5 r90 bottom locked
C759 "GRM155R71A104KA01D" 0402L 46,101.5 r90 bottom
C760 "GRM155R71A104KA01D" 0402L 31,101.5 r90 bottom
C761 "GRM155R71A104KA01D" 0402L 16,101.5 r90 bottom
C762 "GRM155R71A104KA01D" 0402L 76,119 r90 bottom
C763 "GRM155R71A104KA01D" 0402L 61,119 r90 bottom
C764 "GRM155R71A104KA01D" 0402L 46,119 r90 bottom
C765 "GRM155R71A104KA01D" 0402L 31,119 r90 bottom
C766 "GRM155R71A104KA01D" 0402L 16,119 r90 bottom
CENTER-TWEETER "RCJ-024" CONN_RCJ-024 10,111.5 r180 top locked
CENTER-WOOFER "RCJ-024" CONN_RCJ-024 10,129 r180 top locked
CT+ "Center Tweeter+" TEC-SpadeLug_63066-1 345,77.5 r90 top
CT- "Center Tweeter-" TEC-SpadeLug_63066-1 335,77.5 r90 top
CW+ "Center Woofer+" TEC-SpadeLug_63066-1 325,77.5 r90 top
CW- "Center Woofer-" TEC-SpadeLug_63066-1 315,77.5 r90 top
D1 "MODE2" LED_SMLP12_BLUE 209.25,60 r180 top
D2 "MODE3" LED_SMLP12_BLUE 209.25,55 r180 top
D3 "MODE4" LED_SMLP12_BLUE 209.25,50 r180 top
D4 "ACTIVITY" LED_SMLP12_BLUE 206.25,72.5 r180 top
D5 "MODE1" LED_SMLP12_BLUE 209.25,65 r180 top
D6 "MUTE" LED_LTST-C190_Red 209,80 r180 top
D12 "B560C-13-F" SMC 381.75,72.25 r180 bottom
D13 "3.3V-MAIN/SUB" LED_LTST-C171 385,17.5 r0 top
D14 "3.3V-SURR/UP/FR" LED_LTST-C171 385,12.5 r0 top
D15 "3.3V-FL/CENTER" LED_LTST-C171 385,7.5 r0 top
D700 "3.3V" LED_LTST-C171 78,92.5 r90 top
DIN2-SEL "" PBC03SAAN 225,40 r180 top
FAULT "" LED_LTST-C170_Red 233.75,3.75 r180 top
FID1 "Fiducial" Fiducial10-20 11,5 r0 top
FID2 "Fiducial" Fiducial10-20 5,75 r0 top
FID3 "Fiducial" Fiducial10-20 395,15 r0 top
FID4 "Fiducial" Fiducial10-20 395,15 r180 bottom
FID5 "Fiducial" Fiducial10-20 11,5 r180 bottom
FID6 "Fiducial" Fiducial10-20 5,75 r180 bottom
FID7 "Fiducial" Fiducial10-20 77.5,132.5 r180 bottom
FID8 "Fiducial" Fiducial10-20 2.5,87.5 r180 bottom
FID9 "Fiducial" Fiducial10-20 2.5,132.5 r180 bottom
FL-TWEETER "RCJ-024" CONN_RCJ-024 25,111.5 r180 top locked
FL-WOOFER "RCJ-024" CONN_RCJ-024 25,129 r180 top locked
FLT+ "Front Left Tweeter+" TEC-SpadeLug_63066-1 285,77.5 r90 top
FLT- "Front Left Tweeter-" TEC-SpadeLug_63066-1 275,77.5 r90 top
FLW+ "Front Left Woofer+" TEC-SpadeLug_63066-1 265,77.5 r90 top
FLW- "Front Left Woofer-" TEC-SpadeLug_63066-1 255,77.5 r90 top
FR-TWEETER "RCJ-024" CONN_RCJ-024 40,111.5 r180 top locked
FR-WOOFER "RCJ-024" CONN_RCJ-024 40,129 r180 top locked
FRT+ "Front Right Tweeter+" TEC-SpadeLug_63066-1 165,77.5 r90 top
FRT- "Front Right Tweeter-" TEC-SpadeLug_63066-1 155,77.5 r90 top
FRW+ "Front Right Woofer+" TEC-SpadeLug_63066-1 145,77.5 r90 top
FRW- "Front Right Woofer-" TEC-SpadeLug_63066-1 135,77.5 r90 top
GND-IN "DNP" Keystone5001 372.5,76.25 r90 top
H1 "Spacer" Bivar_9912-250 396,81 r180 bottom
H2 "Spacer" Bivar_9912-250 396,4 r180 bottom
H3 "Spacer" Bivar_9912-250 4,81 r180 bottom
H4 "Spacer" Bivar_9912-250 300,4 r180 bottom
H5 "Spacer" Bivar_9912-250 300,70 r180 bottom
H6 "Spacer" Bivar_9912-250 212.25,41 r180 bottom
H7 "Spacer" Bivar_9912-250 120,4 r180 bottom
H8 "Spacer" Bivar_9912-250 120,70 r180 bottom
H9 "Spacer" Bivar_9912-250 4,4 r180 bottom
H10 "Washer" Keystone_3205 396,4 r0 top
H11 "Washer" Keystone_3205 300,4 r0 top
H12 "Washer" Keystone_3205 300,70 r0 top
H13 "Washer" Keystone_3205 212.25,41 r0 top
H14 "Washer" Keystone_3205 120,4 r0 top
H15 "Washer" Keystone_3205 120,70 r0 top
H16 "Washer" Keystone_3205 4,4 r0 top
H17 "Washer" Keystone_3205 4,81 r0 top
H18 "Washer" Keystone_3205 396,81 r0 top
I2S-IN "" Sullins_SBH11-xxxC-D10-ST 205,17.5 r180 top locked
I2S-OUT "SBH11-PBPC-D10-ST-BK" Sullins_SBH11-xxxC-D10-ST 220,17.5 r180 top locked
J1 "0.50\"" WireJumper_923345-05-C 239.5,27.5 r270 bottom
J2 "IDH25" 3M_N2550-6002-RB 190,48.75 r0 top locked
J4 "0.70\"" CONN_923345-07-C 246.25,72 r65 bottom locked
J5 "2\"" 3M_923345-20-C 221.25,82.5 r180 bottom
J6 "3\"" 3M_923345-30-C 225,2.5 r180 bottom locked
J8 "5\"" 3M_923345-50-C 303,35.75 r0 bottom locked
J11 "PBC02SAAN" Sullins_PBC02SAAN 229.75,47.5 r0 top
J600 "0.70\"" CONN_923345-07-C 218.25,51.5 r90 bottom
J601 "0.70\"" CONN_923345-07-C 220.5,51.5 r90 bottom locked
J700 "IDH25" 3M_N2550-6002-RB 40,92.5 r270 top locked
JP100 "PBC03SAAN" PBC03SAAN 50,18.75 r180 top
JP101 "PBC03SAAN" PBC03SAAN 40,18.75 r180 top
JP102 "PBC03SAAN" PBC03SAAN 20,18.75 r180 top
JP103 "PBC03SAAN" PBC03SAAN 10,18.75 r180 top
JP200 "PBC03SAAN" PBC03SAAN 110,18.75 r180 top
JP201 "PBC03SAAN" PBC03SAAN 100,18.75 r180 top
JP202 "PBC03SAAN" PBC03SAAN 80,18.75 r180 top
JP203 "PBC03SAAN" PBC03SAAN 70,18.75 r180 top
JP300 "PBC03SAAN" PBC03SAAN 170,18.75 r180 top
JP301 "PBC03SAAN" PBC03SAAN 160,18.75 r180 top
JP302 "PBC03SAAN" PBC03SAAN 140,18.75 r180 top
JP303 "PBC03SAAN" PBC03SAAN 130,18.75 r180 top
JP400 "PBC03SAAN" PBC03SAAN 290,18.75 r180 top
JP401 "PBC03SAAN" PBC03SAAN 280,18.75 r180 top
JP402 "PBC03SAAN" PBC03SAAN 260,18.75 r180 top
JP403 "PBC03SAAN" PBC03SAAN 250,18.75 r180 top
JP500 "PBC03SAAN" PBC03SAAN 350,18.75 r180 top
JP501 "PBC03SAAN" PBC03SAAN 340,18.75 r180 top
JP502 "PBC03SAAN" PBC03SAAN 320,18.75 r180 top
JP503 "PBC03SAAN" PBC03SAAN 310,18.75 r180 top
JTAG "851-43-006-10-001000" Mill-Max_851-XX-006-10-001000 223.75,47.5 r90 top
L1 "7447714101" WE-PD_1050 393,71.25 r270 top
L100 "GLFR1608T100M-LR" 0603L 38.75,27.75 r180 top
L101 "UA8014-ALD" Coilcraft_RA7231-ALB 40,61.25 r180 top locked
L102 "UA8014-ALD" Coilcraft_RA7231-ALB 20,61.25 r180 top locked
L200 "GLFR1608T100M-LR" 0603L 98.75,27.75 r180 top
L201 "UA8014-ALD" Coilcraft_RA7231-ALB 100,61.25 r180 top
L202 "UA8014-ALD" Coilcraft_RA7231-ALB 80,61.25 r180 top
L300 "GLFR1608T100M-LR" 0603L 158.75,27.75 r180 top
L301 "UA8014-ALD" Coilcraft_RA7231-ALB 160,61.25 r180 top
L302 "UA8014-ALD" Coilcraft_RA7231-ALB 140,61.25 r180 top
L400 "GLFR1608T100M-LR" 0603L 278.75,27.75 r180 top
L401 "UA8014-ALD" Coilcraft_RA7231-ALB 280,61.25 r180 top
L402 "UA8014-ALD" Coilcraft_RA7231-ALB 260,61.25 r180 top
L500 "GLFR1608T100M-LR" 0603L 338.75,27.75 r180 top
L501 "UA8014-ALD" Coilcraft_RA7231-ALB 340,61.25 r180 top
L502 "UA8014-ALD" Coilcraft_RA7231-ALB 320,61.25 r180 top
L600 "NRS4012T100MDGJV" NRS4012 241,70.75 r90 bottom
L700 "NRS4012T100MDGJV" NRS4012 74.25,92.5 r90 bottom
LOAD "" SW_TL1015AF160QG 200,45 r0 top
Logo2 "Pb-Free Symbol" Pb-Free_Overlay_Small 172.5,6.25 r0 top
Logo3 "FCC disclaimer" FCC_disclaimer_stacked 172.5,2.5 r0 top
Logo5 "Pb-Free Symbol" Pb-Free_Overlay_Small 10,100 r0 top
Logo6 "FCC disclaimer" FCC_disclaimer_stacked 10,103.75 r0 top
MODE1 "" SW_TL1015AF160QG 200,65 r0 top
MODE2 "" SW_TL1015AF160QG 200,60 r0 top
MODE3 "" SW_TL1015AF160QG 200,55 r0 top
MODE4 "" SW_TL1015AF160QG 200,50 r0 top
MUTE "" SW_TL1015AF160QG 200,80 r0 top
OTW "" LTST-C170KFKT_Orange 233.75,8.75 r180 top
PWR-IN "DNP" Keystone5000 372.5,81.25 r90 top
Q1 "2N7002-7-F" SOT-23 242.5,8.75 r180 top
Q2 "MMBT2222A" SOT-23 212.5,65 r180 bottom
Q3 "2N7002-7-F" SOT-23 242.5,3.75 r180 top
Q4 "MMBT2222A" SOT-23 212.5,61.25 r180 bottom
Q5 "MMBT2222A" SOT-23 211.25,57 r270 bottom
Q6 "MMBT2222A" SOT-23 209.125,46.25 r90 bottom
Q7 "MMBT2222A" SOT-23 208.25,68.75 r180 bottom
Q8 "MMBT2222A" SOT-23 212.5,68.75 r180 bottom
R1 "CRCW0402100KFKED" 0402L 224.5,66.5 r0 top
R2 "CRCW06030000Z0EA" 0603L 240.75,59.25 r0 top
R3 "ERJ-2RKF2001X" 0402L 238.5,19.25 r0 top
R4 "ERJ-2RKF2001X" 0402L 238.5,18 r0 top
R5 "ERJ-2RKF2001X" 0402L 236.5,12.5 r270 top
R6 "ERJ-2RKF2001X" 0402L 235.5,12.5 r270 top
R7 "ERJ-2RKF2001X" 0402L 234.5,12.5 r270 top
R8 "ERJ-2RKF2001X" 0402L 233.5,12.5 r270 top
R9 "ERJ-2RKF2001X" 0402L 232.5,12.5 r270 top
R10 "ERJ-2RKF2001X" 0402L 231.5,12.5 r270 top
R11 "ERJ-2RKF2001X" 0402L 230.5,12.5 r270 top
R12 "ERJ-2RKF2001X" 0402L 236.5,54 r270 bottom
R13 "ERJ-2RKF2001X" 0402L 234,54 r270 bottom
R14 "ERJ-2RKF2001X" 0402L 229.5,12.5 r270 top
R15 "ERJ-2RKF2001X" 0402L 228.5,12.5 r270 top
R16 "ERJ-2RKF2001X" 0402L 227.5,12.5 r270 top
R17 "RC0603FR-0730KL" 0603L 31.25,23.25 r0 top
R18 "CRCW06031K00FKEA" 0603L 236.5,9.5 r270 top
R19 "RC0603JR-0747KL" 0603L 242.5,19.25 r180 top
R20 "CRCW0603100RFKEA" 0603L 246.25,7.75 r0 top
R21 "CRCW06030000Z0EA" 0603L 20.25,28.25 r0 bottom
R22 "CRCW06030000Z0EA" 0603L 80.25,28.25 r0 bottom
R23 "CRCW06030000Z0EA" 0603L 140,28.25 r0 bottom
R24 "CRCW06030000Z0EA" 0603L 259.25,26 r90 bottom
R25 "CRCW06030000Z0EA" 0603L 325,20 r90 bottom
R26 "CRCW06031K00FKEA" 0603L 236.75,4.5 r270 top
R27 "RC0603JR-0747KL" 0603L 242.5,18 r180 bottom
R28 "CRCW0603100RFKEA" 0603L 246.25,2.75 r0 top
R29 "CRCW06030000Z0EA" 0603L 22.5,26.25 r0 bottom
R30 "CRCW06030000Z0EA" 0603L 82.5,26.25 r0 bottom
R31 "CRCW06030000Z0EA" 0603L 141.25,25.25 r0 bottom
R32 "CRCW06030000Z0EA" 0603L 261.25,25.25 r0 bottom
R33 "CRCW06030000Z0EA" 0603L 326.25,20 r90 bottom
R34 "CRCW0603215KFKEA" 0603L 387,81.375 r90 bottom
R35 "DNP" 0603L 375.75,79.75 r270 bottom
R36 "CRCW060325K5FKEA" 0603L 388.25,78.625 r90 bottom
R37 "CRCW060312K1FKEA" 0603L 388.875,80.625 r180 bottom
R38 "CRCW040233K2FKED" 0402L 207,64 r90 bottom
R39 "CRCW040233K2FKED" 0402L 207,61 r270 bottom
R40 "CRCW040233K2FKED" 0402L 207,59 r90 bottom
R41 "CRCW040247K5FKED" 0402L 221.25,51 r0 top
R42 "CRCW040233K2FKED" 0402L 207,56 r270 bottom
R43 "CRCW0402332RFKED" 0402L 219.75,47.5 r270 top
R44 "CRCW040233K2FKED" 0402L 207,54 r90 bottom
R45 "CRCW040233K2FKED" 0402L 207,46 r270 bottom
R46 "ERJ-2RKF1000X" 0402L 209.25,65 r0 bottom
R47 "DNP" 0603L 377,81.25 r270 bottom
R48 "RC0603FR-07150KL" 0603L 378.25,81.25 r270 bottom
R49 "CRCW12060000Z0EA" 1206L 366.25,55 r0 bottom
R50 "CRCW04022K15FKED" 0402L 216,66 r0 bottom
R51 "CRCW0402360RJNED" 0402L 386.75,17.5 r180 bottom
R52 "CRCW0402360RJNED" 0402L 386.75,12.5 r180 bottom
R53 "CRCW0402360RJNED" 0402L 386.75,7.5 r180 bottom
R54 "CRCW060310K0FKEA" 0603L 26,25.25 r0 bottom
R55 "CRCW060310K0FKEA" 0603L 86,25.25 r0 bottom
R56 "CRCW060310K0FKEA" 0603L 146,25.25 r0 bottom
R57 "CRCW060310K0FKEA" 0603L 266,25.25 r0 bottom
R58 "CRCW060310K0FKEA" 0603L 326,25.25 r0 bottom
R59 "CRCW040210K0FKED" 0402L 231,28 r0 top
R60 "CRCW040233K2FKED" 0402L 207,51 r270 bottom
R61 "CRCW040233K2FKED" 0402L 207,49 r90 bottom
R62 "ERJ-2RKF1000X" 0402L 209.25,60 r0 bottom
R63 "CRCW04022K15FKED" 0402L 216,62.25 r0 bottom
R64 "CRCW0402100KFKED" 0402L 240.5,58 r0 top
R65 "ERJ-2RKF1000X" 0402L 209.25,55 r0 bottom
R66 "CRCW060310K0FKEA" 0603L 229.75,23 r180 top
R67 "CRCW04022K15FKED" 0402L 214.25,57.25 r0 bottom
R68 "ERJ-2RKF1000X" 0402L 208.75,49.5 r270 bottom
R69 "CRCW04022K15FKED" 0402L 216.25,46.875 r0 bottom
R70 "ERJ-2RKF1000X" 0402L 205.75,69.25 r270 bottom
R71 "CRCW04022K15FKED" 0402L 216,71.25 r0 bottom
R72 "ERJ-2RKF1000X" 0402L 211.25,80 r0 bottom
R73 "CRCW04022K15FKED" 0402L 216,69.75 r0 bottom
R74 "CRCW040247K5FKED" 0402L 206,41.25 r0 bottom
R75 "CRCW040249R9FKED" 0402L 28.75,5.75 r270 top
R76 "CRCW040249R9FKED" 0402L 88.75,5.75 r270 top
R77 "CRCW040249R9FKED" 0402L 148.75,5.75 r270 top
R78 "CRCW040249R9FKED" 0402L 268.75,5.75 r270 top
R79 "CRCW040249R9FKED" 0402L 328.75,5.75 r270 top
R80 "CRCW040249R9FKED" 0402L 213.625,10.625 r180 bottom
R81 "CRCW040249R9FKED" 0402L 27.75,5.75 r270 top
R82 "CRCW040249R9FKED" 0402L 87.75,5.75 r270 top
R83 "CRCW040249R9FKED" 0402L 147.75,5.75 r270 top
R84 "CRCW040249R9FKED" 0402L 267.75,5.75 r270 top
R85 "CRCW040249R9FKED" 0402L 327.75,5.75 r270 top
R86 "CRCW040249R9FKED" 0402L 211.125,15 r270 bottom
R87 "CRCW040249R9FKED" 0402L 30.75,5.75 r270 top
R88 "CRCW040249R9FKED" 0402L 90.75,5.75 r270 top
R89 "CRCW040249R9FKED" 0402L 150.75,5.75 r270 top
R90 "CRCW040249R9FKED" 0402L 270.75,5.75 r270 top
R91 "CRCW040249R9FKED" 0402L 330.75,5.75 r270 top
R92 "CRCW040249R9FKED" 0402L 213.625,7.375 r180 bottom
R93 "CRCW06030000Z0EA" 0603L 237.5,65 r180 top
R94 "DNP" 0603L 237.5,63.75 r180 top
R100 "CRCW060310R0JNEA" 0603L 24.75,13.875 r0 top
R101 "CRCW0603499RFKEA" 0603L 33.125,14.375 r0 top
R102 "CRCW0603100RFKEA" 0603L 44.5,22.5 r180 top
R103 "CRCW0603499RFKEA" 0603L 33.125,15.75 r0 top
R104 "CRCW06033R30JNEA" 0603L 41.25,74.25 r90 bottom
R105 "CRCW0603499RFKEA" 0603L 27.5,16.25 r180 top
R106 "CRCW0603100RFKEA" 0603L 34.5,22.5 r180 top
R107 "CRCW0603499RFKEA" 0603L 27.5,15 r180 top
R108 "CRCW0603100RFKEA" 0603L 25.5,22.5 r0 top
R109 "CRCW06033R30JNEA" 0603L 31.25,74.25 r90 bottom
R110 "DNP" 0402L 32.625,6 r270 top
R111 "DNP" 0402L 26,10.25 r180 top
R112 "ERJ-2RKF1002X" 0402L 33.5,6 r90 top
R113 "ERJ-2RKF1002X" 0402L 31.75,6 r90 top
R114 "ERJ-2RKF1002X" 0402L 26,9.375 r0 top
R115 "CRCW04024K99FKED" 0402L 26,8.5 r180 top
R116 "CRCW0603100RFKEA" 0603L 15.5,22.5 r0 top
R117 "CRCW04024K99FKED" 0402L 26,7.625 r180 top
R118 "CRCW06033R30JNEA" 0603L 28.75,74.25 r90 bottom
R119 "RC0603FR-0722KL" 0603L 31.25,22 r0 top
R120 "CRCW06033R30JNEA" 0603L 18.75,74.25 r90 bottom
R200 "CRCW060310R0JNEA" 0603L 84.75,13.875 r0 top
R201 "CRCW0603499RFKEA" 0603L 93.125,14.375 r0 top
R202 "CRCW0603100RFKEA" 0603L 104.5,22.5 r180 top
R203 "CRCW0603499RFKEA" 0603L 93.125,15.75 r0 top
R204 "CRCW06033R30JNEA" 0603L 101.25,74.25 r90 bottom
R205 "CRCW0603499RFKEA" 0603L 87.5,16.25 r180 top
R206 "CRCW0603100RFKEA" 0603L 94.5,22.5 r180 top
R207 "CRCW0603499RFKEA" 0603L 87.5,15 r180 top
R208 "CRCW0603100RFKEA" 0603L 85.5,22.5 r0 top
R209 "CRCW06033R30JNEA" 0603L 91.25,74.25 r90 bottom
R210 "DNP" 0402L 92.625,6 r270 top
R211 "DNP" 0402L 86,10.25 r180 top
R212 "ERJ-2RKF1002X" 0402L 93.5,6 r90 top
R213 "ERJ-2RKF1002X" 0402L 91.75,6 r90 top
R214 "ERJ-2RKF1002X" 0402L 86,9.375 r0 top
R215 "CRCW04024K99FKED" 0402L 86,8.5 r180 top
R216 "CRCW0603100RFKEA" 0603L 75.5,22.5 r0 top
R217 "CRCW04024K99FKED" 0402L 86,7.625 r180 top
R218 "CRCW06033R30JNEA" 0603L 88.75,74.25 r90 bottom
R219 "RC0603FR-0722KL" 0603L 91.25,22 r0 top
R220 "CRCW06033R30JNEA" 0603L 78.75,74.25 r90 bottom
R300 "CRCW060310R0JNEA" 0603L 144.75,13.875 r0 top
R301 "CRCW0603499RFKEA" 0603L 153.125,14.375 r0 top
R302 "CRCW0603100RFKEA" 0603L 164.5,22.5 r180 top
R303 "CRCW0603499RFKEA" 0603L 153.125,15.75 r0 top
R304 "CRCW06033R30JNEA" 0603L 161.25,74.25 r90 bottom
R305 "CRCW0603499RFKEA" 0603L 147.5,16.25 r180 top
R306 "CRCW0603100RFKEA" 0603L 154.5,22.5 r180 top
R307 "CRCW0603499RFKEA" 0603L 147.5,15 r180 top
R308 "CRCW0603100RFKEA" 0603L 145.5,22.5 r0 top
R309 "CRCW06033R30JNEA" 0603L 151.25,74.25 r90 bottom
R310 "DNP" 0402L 152.625,6 r270 top
R311 "DNP" 0402L 146,10.25 r180 top
R312 "ERJ-2RKF1002X" 0402L 153.5,6 r90 top
R313 "ERJ-2RKF1002X" 0402L 151.75,6 r90 top
R314 "ERJ-2RKF1002X" 0402L 146,9.375 r0 top
R315 "CRCW04024K99FKED" 0402L 146,8.5 r180 top
R316 "CRCW0603100RFKEA" 0603L 135.5,22.5 r0 top
R317 "CRCW04024K99FKED" 0402L 146,7.625 r180 top
R318 "CRCW06033R30JNEA" 0603L 148.75,74.25 r90 bottom
R319 "RC0603FR-0722KL" 0603L 151.25,22 r0 top
R320 "CRCW06033R30JNEA" 0603L 138.75,74.25 r90 bottom
R400 "CRCW060310R0JNEA" 0603L 264.75,13.875 r0 top
R401 "CRCW0603499RFKEA" 0603L 273.125,14.375 r0 top
R402 "CRCW0603100RFKEA" 0603L 284.5,22.5 r180 top
R403 "CRCW0603499RFKEA" 0603L 273.125,15.75 r0 top
R404 "CRCW06033R30JNEA" 0603L 281.25,74.25 r90 bottom
R405 "CRCW0603499RFKEA" 0603L 267.5,16.25 r180 top
R406 "CRCW0603100RFKEA" 0603L 274.5,22.5 r180 top
R407 "CRCW0603499RFKEA" 0603L 267.5,15 r180 top
R408 "CRCW0603100RFKEA" 0603L 265.5,22.5 r0 top
R409 "CRCW06033R30JNEA" 0603L 271.25,74.25 r90 bottom
R410 "DNP" 0402L 272.625,6 r270 top
R411 "DNP" 0402L 266,10.25 r180 top
R412 "ERJ-2RKF1002X" 0402L 273.5,6 r90 top
R413 "ERJ-2RKF1002X" 0402L 271.75,6 r90 top
R414 "ERJ-2RKF1002X" 0402L 266,9.375 r0 top
R415 "CRCW04024K99FKED" 0402L 266,8.5 r180 top
R416 "CRCW0603100RFKEA" 0603L 255.5,22.5 r0 top
R417 "CRCW04024K99FKED" 0402L 266,7.625 r180 top
R418 "CRCW06033R30JNEA" 0603L 268.75,74.25 r90 bottom
R419 "RC0603FR-0722KL" 0603L 271.25,22 r0 top
R420 "CRCW06033R30JNEA" 0603L 258.75,74.25 r90 bottom
R500 "CRCW060310R0JNEA" 0603L 324.75,13.875 r0 top
R501 "CRCW0603499RFKEA" 0603L 333.125,14.375 r0 top
R502 "CRCW0603100RFKEA" 0603L 344.5,22.5 r180 top
R503 "CRCW0603499RFKEA" 0603L 333.125,15.75 r0 top
R504 "CRCW06033R30JNEA" 0603L 341.25,74.25 r90 bottom
R505 "CRCW0603499RFKEA" 0603L 327.5,16.25 r180 top
R506 "CRCW0603100RFKEA" 0603L 334.5,22.5 r180 top
R507 "CRCW0603499RFKEA" 0603L 327.5,15 r180 top
R508 "CRCW0603100RFKEA" 0603L 325.5,22.5 r0 top
R509 "CRCW06033R30JNEA" 0603L 331.25,74.25 r90 bottom
R510 "DNP" 0402L 332.625,6 r270 top
R511 "DNP" 0402L 326,10.25 r180 top
R512 "ERJ-2RKF1002X" 0402L 333.5,6 r90 top
R513 "ERJ-2RKF1002X" 0402L 331.75,6 r90 top
R514 "ERJ-2RKF1002X" 0402L 326,9.375 r0 top
R515 "CRCW04024K99FKED" 0402L 326,8.5 r180 top
R516 "CRCW0603100RFKEA" 0603L 315.5,22.5 r0 top
R517 "CRCW04024K99FKED" 0402L 326,7.625 r180 top
R518 "CRCW06033R30JNEA" 0603L 328.75,74.25 r90 bottom
R519 "RC0603FR-0722KL" 0603L 331.25,22 r0 top
R520 "CRCW06033R30JNEA" 0603L 318.75,74.25 r90 bottom
R600 "ERJ-2RKF1002X" 0402L 233.75,71.5 r270 bottom
R601 "CRCW060310R0JNEA" 0603L 222.25,63.875 r0 top
R602 "CRCW0603499RFKEA" 0603L 227.5,64.5 r90 top
R603 "CRCW0603100RFKEA" 0603L 225.75,65.25 r180 top
R604 "ERJ-2RKF1002X" 0402L 222,70 r180 top
R605 "CRCW060349R9FKEA" 0603L 230.25,73.5 r180 bottom
R606 "ERJ-2RKF1002X" 0402L 233.75,68.75 r270 bottom
R607 "CRCW0603499RFKEA" 0603L 228.75,64.5 r90 top
R608 "CRCW0603100RFKEA" 0603L 230.5,65.25 r0 top
R609 "ERJ-2RKF1002X" 0402L 234,70 r0 top
R610 "ERJ-2RKF1002X" 0402L 237,70 r270 bottom
R611 "ERJ-2RKF1002X" 0402L 236,70 r90 bottom
R612 "DNP" 0402L 230.125,56 r270 top
R613 "DNP" 0402L 223.5,60.25 r180 top
R614 "ERJ-2RKF1002X" 0402L 231,56 r90 top
R615 "ERJ-2RKF1002X" 0402L 229.25,56 r90 top
R616 "ERJ-2RKF1002X" 0402L 223.5,59.375 r0 top
R617 "CRCW04024K99FKED" 0402L 223.5,58.5 r180 top
R618 "CRCW04024K99FKED" 0402L 223.5,57.625 r180 top
R619 "CRCW0402100KFKED" 0402L 225.5,76.5 r90 bottom
R620 "CRCW0402100KFKED" 0402L 231.75,66.5 r180 top
R700 "ERJ-2RKF1002X" 0402L 66.5,102.25 r90 bottom
R701 "ERJ-2RKF1002X" 0402L 51.5,102.25 r90 bottom
R702 "ERJ-2RKF1002X" 0402L 36.5,102.25 r90 bottom
R703 "ERJ-2RKF1002X" 0402L 21.5,102.25 r90 bottom
R704 "ERJ-2RKF1002X" 0402L 6.5,102.25 r90 bottom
